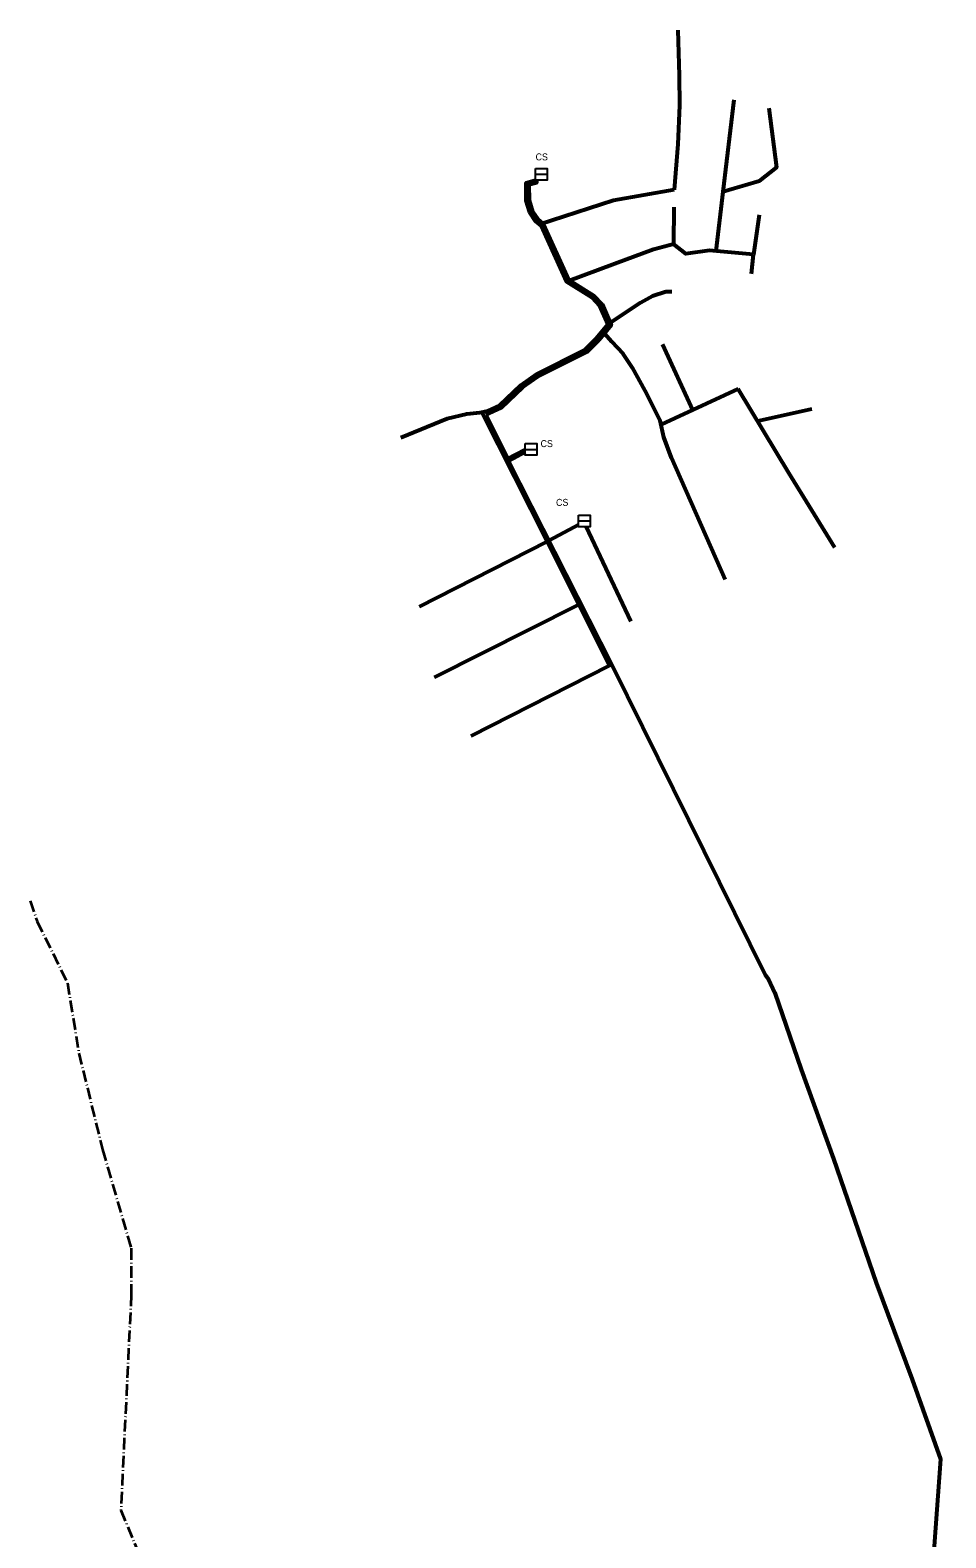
# Model space of a CAD drawing. Extents: x -650270 to -643402, y -1075206 to -1066724.
# Drawn here: x -649363 to -647793, y -1069310 to -1066724 of the extents above; entities that cross this region are included whole.
import ezdxf

# ---------------------------------------------------------------- set-up
doc = ezdxf.new("R2010")
doc.units = 0
doc.header["$LTSCALE"] = 4
doc.linetypes.add('DOT_DASHED', pattern=[7.7, 5, -1.2, 0.3, -1.2])
for name, color, linetype, lineweight in [('17', 7, 'DOT_DASHED', 35), ('41', 7, 'Continuous', 25), ('48', 7, 'Continuous', 53), ('50', 7, 'Continuous', 53)]:
    doc.layers.add(name, color=color, linetype=linetype, lineweight=lineweight)
doc.layers.add('42', color=7, linetype='Continuous')

msp = doc.modelspace()

# ---------------------------------------------------------------- linework, layer by layer
at = {"layer": '17'}
msp.add_lwpolyline([(-649363.01, -1068217.61), (-649351.01, -1068252.7), (-649299.051, -1068358.095), (-649279.559, -1068478.668), (-649239.032, -1068644.304), (-649189.693, -1068813.464), (-649189.693, -1068892.758), (-649207.492, -1069262.666), (-648996.866, -1069772.913)], dxfattribs=at)
at = {"layer": '41'}
for p, q in [((-648496.45, -1066970.726), (-648476.45, -1066970.726)), ((-648513.861, -1067442.818), (-648493.861, -1067442.818)), ((-648422.514, -1067565.529), (-648402.514, -1067565.529))]:
    msp.add_line(p, q, dxfattribs=at)
for points in [[(-648496.45, -1066960.726), (-648476.45, -1066960.726), (-648476.45, -1066980.726), (-648496.45, -1066980.726)], [(-648513.861, -1067432.818), (-648493.861, -1067432.818), (-648493.861, -1067452.818), (-648513.861, -1067452.818)], [(-648422.514, -1067555.529), (-648402.514, -1067555.529), (-648402.514, -1067575.529), (-648422.514, -1067575.529)]]:
    msp.add_lwpolyline(points, close=True, dxfattribs=at)
at = {"layer": '48'}
for p, q in [((-648156.188, -1066842.965), (-648175.103, -1067000.787)), ((-648112.923, -1067040.185), (-648122.323, -1067108.492)), ((-648126.215, -1067141.574), (-648122.323, -1067108.492)), ((-648278.693, -1067262.163), (-648226.61, -1067375.798)), ((-648148.861, -1067338.914), (-648280.961, -1067400.28)), ((-648022.455, -1067373.987), (-648115.291, -1067394.71)), ((-648332.957, -1067738.131), (-648409.27, -1067575.529)), ((-648669.671, -1067833.759), (-648423.502, -1067709.352))]:
    msp.add_line(p, q, dxfattribs=at)
for points in [[(-648252.456, -1066723.599), (-648250.264, -1066801.299), (-648249.179, -1066853.014), (-648252.134, -1066919.188), (-648258.793, -1066997.815)], [(-648096.284, -1066857.303), (-648083.325, -1066959.43), (-648112.691, -1066982.613), (-648175.103, -1067000.787), (-648187.091, -1067102.535)], [(-648727.246, -1067422.379), (-648647.817, -1067390.132), (-648614.221, -1067381.691), (-648592.1, -1067379.812), (-648577.987, -1067376.732), (-648558.122, -1067367.651), (-648521.513, -1067332.461), (-648494.27, -1067313.448), (-648411.121, -1067271.731), (-648391.698, -1067252.087), (-648372.527, -1067228.879), (-648386.432, -1067196.527), (-648399.439, -1067182.575), (-648443.031, -1067155.363), (-648486.738, -1067059.306), (-648496.387, -1067051.36), (-648506.036, -1067036.603), (-648512.279, -1067016.171), (-648512.576, -1066985.298), (-648496.45, -1066980.867)], [(-648258.793, -1066997.815), (-648362.765, -1067016.019), (-648489.699, -1067056.867)], [(-648259.317, -1067027.245), (-648259.994, -1067090.616), (-648293.931, -1067099.901), (-648360.204, -1067124.553), (-648443.031, -1067155.363)], [(-648122.323, -1067108.492), (-648198.187, -1067101.515), (-648238.811, -1067107.157), (-648259.994, -1067090.616)], [(-648262.514, -1067172.785), (-648272.991, -1067172.516), (-648295.736, -1067180.056), (-648316.098, -1067191.329), (-648372.527, -1067228.879)], [(-648170.988, -1067666.011), (-648263.147, -1067457.29), (-648276.574, -1067422.029), (-648282.359, -1067393.352), (-648308.398, -1067342.65), (-648329.947, -1067302.999), (-648345.821, -1067279.105), (-648365.719, -1067258.177), (-648381.703, -1067239.987)], [(-647982.89, -1067611.409), (-648062.076, -1067483.157), (-648148.861, -1067338.914)], [(-648695.336, -1067712.244), (-648476.59, -1067601.027), (-648588.603, -1067379.049)], [(-648606.905, -1067934.086), (-648369.38, -1067813.915), (-648476.59, -1067601.027)]]:
    msp.add_lwpolyline(points, dxfattribs=at)
at = {"layer": '50'}
for p, q in [((-648581.443, -1067383.81), (-648543.768, -1067458.601)), ((-648543.768, -1067458.601), (-648513.861, -1067443.194)), ((-648422.514, -1067572.282), (-648472.987, -1067599.112))]:
    msp.add_line(p, q, dxfattribs=at)
for points in [[(-648494.61, -1066980.726), (-648494.61, -1066985.547), (-648507.539, -1066989.099), (-648507.286, -1067015.401), (-648501.462, -1067034.462), (-648492.62, -1067047.985), (-648482.666, -1067056.182), (-648439.104, -1067151.92), (-648396.232, -1067178.683), (-648382.182, -1067193.754), (-648366.728, -1067229.71), (-648387.985, -1067255.444), (-648408.144, -1067275.831), (-648491.705, -1067317.755), (-648518.33, -1067336.337), (-648555.27, -1067371.845), (-648581.443, -1067383.81)], [(-648514.214, -1067447.752), (-648542.513, -1067463.043), (-648365.356, -1067812.774), (-648102.701, -1068344.214), (-648096.618, -1068351.919), (-648085.99, -1068375.178), (-648040.609, -1068506.842), (-647985.265, -1068660.291), (-647912.016, -1068872.532), (-647850.161, -1069038.905)], [(-647850.161, -1069038.905), (-647801.818, -1069175.256), (-647812.644, -1069324.711), (-647825.015, -1069541.552), (-647823.978, -1069584.663), (-647594.109, -1069559.949)]]:
    msp.add_lwpolyline(points, dxfattribs=at)

# ---------------------------------------------------------------- texts
at = {"layer": '42', "width": 0.95}
for p in [(-648496.278, -1066947.064), (-648487.741, -1067438.958), (-648461.215, -1067539.755)]:
    msp.add_text('CS', height=12, dxfattribs=at).set_placement(p)

doc.saveas('drawing.dxf')
